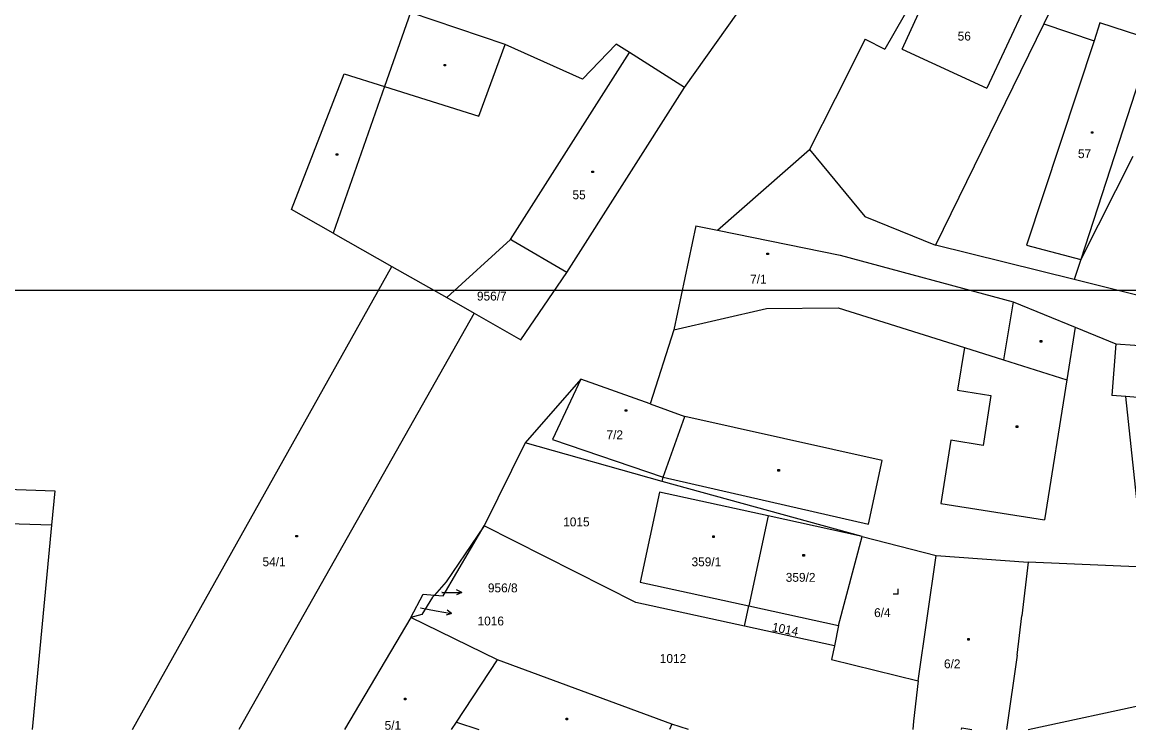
# Model space of a CAD drawing. Extents: x -770973 to -770265, y -1049936 to -1049427.
# Drawn here: x -770637.6 to -770531.6, y -1049934.8 to -1049867 of the extents above; entities that cross this region are included whole.
import ezdxf

# ---------------------------------------------------------------- set-up
doc = ezdxf.new("R2010")
doc.units = 0
for name, color, linetype in [('Vrstva 1', 7, 'Continuous'), ('Vrstva 13', 7, 'Continuous'), ('Vrstva 14', 7, 'Continuous'), ('Vrstva 15', 7, 'Continuous'), ('Vrstva 16', 7, 'Continuous'), ('Vrstva 2', 7, 'Continuous'), ('Vrstva 23', 7, 'Continuous'), ('Vrstva 25', 7, 'Continuous'), ('Vrstva 63', 7, 'Continuous')]:
    doc.layers.add(name, color=color, linetype=linetype)

msp = doc.modelspace()

# ---------------------------------------------------------------- linework, layer by layer
at = {"layer": 'Vrstva 1'}
for p, q in [((-770548.75, -1049858.73), (-770554.96, -1049869.59)), ((-770536.61, -1049860.73), (-770539.76, -1049867.18)), ((-770574.15, -1049873.29), (-770565.62, -1049861.27)), ((-770600.39, -1049866.1), (-770602.87, -1049873.18)), ((-770591.32, -1049869.17), (-770600.39, -1049866.1)), ((-770539.76, -1049867.18), (-770550.11, -1049888.38)), ((-770539.76, -1049867.18), (-770534.94, -1049868.8)), ((-770534.37, -1049867.08), (-770534.94, -1049868.8)), ((-770529.36, -1049868.71), (-770534.37, -1049867.08)), ((-770583.93, -1049872.47), (-770591.32, -1049869.17)), ((-770580.7, -1049869.11), (-770583.93, -1049872.47)), ((-770579.41, -1049869.93), (-770580.7, -1049869.11)), ((-770556.84, -1049868.64), (-770559.74, -1049874.37)), ((-770556.84, -1049868.64), (-770554.96, -1049869.59)), ((-770529.36, -1049868.71), (-770536.21, -1049889.74)), ((-770574.15, -1049873.29), (-770579.41, -1049869.93)), ((-770602.87, -1049873.18), (-770607.79, -1049887.24)), ((-770585.43, -1049890.98), (-770574.15, -1049873.29)), ((-770559.74, -1049874.37), (-770562.2, -1049879.21)), ((-770570.98, -1049886.94), (-770562.2, -1049879.21)), ((-770562.2, -1049879.21), (-770556.89, -1049885.64)), ((-770531.23, -1049879.87), (-770536.21, -1049889.74)), ((-770556.89, -1049885.64), (-770550.11, -1049888.38)), ((-770607.79, -1049887.24), (-770602.19, -1049890.41)), ((-770573.07, -1049886.51), (-770575.19, -1049896.49)), ((-770573.07, -1049886.51), (-770570.98, -1049886.94)), ((-770570.98, -1049886.94), (-770559.25, -1049889.34)), ((-770590.83, -1049887.84), (-770596.92, -1049893.4)), ((-770590.57, -1049887.99), (-770590.83, -1049887.84)), ((-770585.43, -1049890.98), (-770590.57, -1049887.99)), ((-770536.84, -1049891.67), (-770550.11, -1049888.38)), ((-770559.25, -1049889.34), (-770542.68, -1049893.81)), ((-770602.19, -1049890.41), (-770596.92, -1049893.4)), ((-770536.21, -1049889.74), (-770536.84, -1049891.67)), ((-770589.83, -1049897.43), (-770585.43, -1049890.98)), ((-770529.95, -1049893.38), (-770536.84, -1049891.67)), ((-770596.92, -1049893.4), (-770594.31, -1049894.88)), ((-770542.68, -1049893.81), (-770536.74, -1049896.24)), ((-770594.31, -1049894.88), (-770616.82, -1049934.76)), ((-770594.31, -1049894.88), (-770589.83, -1049897.43)), ((-770575.19, -1049896.49), (-770577.44, -1049903.59)), ((-770536.74, -1049896.24), (-770532.86, -1049897.82)), ((-770532.86, -1049897.82), (-770533.23, -1049902.78)), ((-770532.86, -1049897.82), (-770518.01, -1049898.94)), ((-770584.09, -1049901.21), (-770589.41, -1049907.3)), ((-770577.44, -1049903.59), (-770584.09, -1049901.21)), ((-770531.91, -1049902.88), (-770533.23, -1049902.78)), ((-770530.61, -1049914.85), (-770531.91, -1049902.88)), ((-770527.38, -1049903.22), (-770531.91, -1049902.88)), ((-770577.44, -1049903.59), (-770574.11, -1049904.78)), ((-770576.2, -1049910.61), (-770574.11, -1049904.78)), ((-770589.41, -1049907.3), (-770593.33, -1049915.27)), ((-770576.3, -1049911.01), (-770589.41, -1049907.3)), ((-770576.3, -1049911.01), (-770576.2, -1049910.61)), ((-770557.14, -1049916.29), (-770576.3, -1049911.01)), ((-770576.56, -1049912.05), (-770578.41, -1049920.66)), ((-770566.13, -1049914.31), (-770576.56, -1049912.05)), ((-770566.13, -1049914.31), (-770567.99, -1049922.92)), ((-770557.14, -1049916.29), (-770566.13, -1049914.31)), ((-770597.25, -1049921.95), (-770593.33, -1049915.27)), ((-770593.33, -1049915.27), (-770596.97, -1049920.62)), ((-770578.83, -1049922.61), (-770593.33, -1049915.27)), ((-770559.4, -1049924.79), (-770557.14, -1049916.29)), ((-770557.14, -1049916.29), (-770550.07, -1049918.09)), ((-770551.77, -1049930.12), (-770550.07, -1049918.09)), ((-770550.07, -1049918.09), (-770541.25, -1049918.75)), ((-770530.13, -1049919.21), (-770541.25, -1049918.75)), ((-770596.97, -1049920.62), (-770598.09, -1049921.89)), ((-770578.41, -1049920.66), (-770567.99, -1049922.92)), ((-770600.35, -1049924.04), (-770599.19, -1049921.81)), ((-770598.27, -1049922.09), (-770599.29, -1049923.76)), ((-770599.19, -1049921.81), (-770598.09, -1049921.89)), ((-770598.09, -1049921.89), (-770598.27, -1049922.09)), ((-770598.09, -1049921.89), (-770597.25, -1049921.95)), ((-770568.4, -1049924.87), (-770578.83, -1049922.61)), ((-770568.4, -1049924.87), (-770567.99, -1049922.92)), ((-770567.99, -1049922.92), (-770559.4, -1049924.79)), ((-770600.35, -1049924.04), (-770606.7, -1049934.76)), ((-770599.29, -1049923.76), (-770600.35, -1049924.04)), ((-770592.06, -1049928.08), (-770600.35, -1049924.04)), ((-770559.79, -1049926.76), (-770568.4, -1049924.87)), ((-770559.4, -1049924.79), (-770559.79, -1049926.76)), ((-770559.79, -1049926.76), (-770560.08, -1049928.06)), ((-770575.37, -1049934.25), (-770592.06, -1049928.08)), ((-770560.08, -1049928.06), (-770551.77, -1049930.12)), ((-770551.77, -1049930.12), (-770552.23, -1049933.96)), ((-770541.24, -1049934.76), (-770529.39, -1049932.21)), ((-770552.23, -1049933.96), (-770552.3, -1049934.76)), ((-770575.37, -1049934.25), (-770575.59, -1049934.76)), ((-770573.77, -1049934.76), (-770575.37, -1049934.25)), ((-770547.63, -1049934.76), (-770547.61, -1049934.62)), ((-770547.61, -1049934.62), (-770546.65, -1049934.76))]:
    msp.add_line(p, q, dxfattribs=at)
at = {"layer": 'Vrstva 13'}
for p, q in [((-770597.38, -1049921.63), (-770596.98, -1049921.63)), ((-770599.44, -1049923.1), (-770597.92, -1049923.39))]:
    msp.add_line(p, q, dxfattribs=at)
at = {"layer": 'Vrstva 16'}
for p, q in [((-770596.98, -1049921.63), (-770595.48, -1049921.63)), ((-770595.48, -1049921.63), (-770595.98, -1049921.38)), ((-770595.48, -1049921.63), (-770595.98, -1049921.88)), ((-770597.92, -1049923.39), (-770596.45, -1049923.67)), ((-770596.45, -1049923.67), (-770596.89, -1049923.33)), ((-770596.45, -1049923.67), (-770596.98, -1049923.82))]:
    msp.add_line(p, q, dxfattribs=at)
at = {"layer": 'Vrstva 2'}
for p, q in [((-770553.32, -1049869.61), (-770549.58, -1049861.49)), ((-770541.43, -1049865.29), (-770545.19, -1049873.35)), ((-770593.84, -1049876.01), (-770591.32, -1049869.17)), ((-770534.94, -1049868.8), (-770541.42, -1049888.39)), ((-770590.83, -1049887.84), (-770579.41, -1049869.93)), ((-770553.32, -1049869.61), (-770545.19, -1049873.35)), ((-770611.8, -1049884.97), (-770606.74, -1049871.96)), ((-770606.74, -1049871.96), (-770602.87, -1049873.18)), ((-770602.87, -1049873.18), (-770593.84, -1049876.01)), ((-770607.79, -1049887.24), (-770611.8, -1049884.97)), ((-770541.42, -1049888.39), (-770536.21, -1049889.74)), ((-770627.01, -1049934.76), (-770602.19, -1049890.41)), ((-770575.19, -1049896.49), (-770566.31, -1049894.45)), ((-770566.31, -1049894.45), (-770559.44, -1049894.37)), ((-770559.44, -1049894.37), (-770547.34, -1049898.18)), ((-770542.68, -1049893.81), (-770543.61, -1049899.36)), ((-770536.74, -1049896.24), (-770537.54, -1049901.27)), ((-770547.34, -1049898.18), (-770548, -1049902.28)), ((-770547.34, -1049898.18), (-770543.61, -1049899.36)), ((-770543.61, -1049899.36), (-770537.54, -1049901.27)), ((-770584.09, -1049901.21), (-770586.78, -1049907)), ((-770537.54, -1049901.27), (-770539.67, -1049914.69)), ((-770548, -1049902.28), (-770544.81, -1049902.79)), ((-770544.81, -1049902.79), (-770545.57, -1049907.56)), ((-770555.24, -1049909), (-770574.11, -1049904.78)), ((-770586.78, -1049907), (-770576.2, -1049910.61)), ((-770548.66, -1049907.07), (-770549.62, -1049913.11)), ((-770545.57, -1049907.56), (-770548.66, -1049907.07)), ((-770556.54, -1049915.1), (-770555.24, -1049909)), ((-770576.2, -1049910.61), (-770556.54, -1049915.1)), ((-770643.29, -1049911.61), (-770634.44, -1049911.9)), ((-770634.44, -1049911.9), (-770634.76, -1049915.2)), ((-770549.62, -1049913.11), (-770539.67, -1049914.69)), ((-770634.76, -1049915.2), (-770643.67, -1049914.92)), ((-770634.76, -1049915.2), (-770636.62, -1049934.76)), ((-770541.25, -1049918.75), (-770541.85, -1049923.87)), ((-770542.29, -1049927.65), (-770541.85, -1049923.87)), ((-770595.99, -1049934.06), (-770592.06, -1049928.08)), ((-770542.29, -1049927.65), (-770543.33, -1049934.76)), ((-770596.45, -1049934.76), (-770595.99, -1049934.06)), ((-770595.99, -1049934.06), (-770593.84, -1049934.76))]:
    msp.add_line(p, q, dxfattribs=at)
at = {"layer": 'Vrstva 23'}
for q in [(-770554.18, -1049921.79), (-770553.68, -1049921.29)]:
    msp.add_line((-770553.68, -1049921.79), q, dxfattribs=at)
at = {"layer": 'Vrstva 25'}
for p, q in [((-770597.18, -1049871.06), (-770597.03, -1049871.06)), ((-770597.18, -1049871.21), (-770597.18, -1049871.06)), ((-770597.03, -1049871.21), (-770597.18, -1049871.21)), ((-770597.03, -1049871.06), (-770597.03, -1049871.21)), ((-770535.19, -1049877.51), (-770535.04, -1049877.51)), ((-770535.19, -1049877.66), (-770535.19, -1049877.51)), ((-770535.04, -1049877.66), (-770535.19, -1049877.66)), ((-770535.04, -1049877.51), (-770535.04, -1049877.66)), ((-770607.51, -1049879.62), (-770607.36, -1049879.62)), ((-770607.51, -1049879.77), (-770607.51, -1049879.62)), ((-770607.36, -1049879.77), (-770607.51, -1049879.77)), ((-770607.36, -1049879.62), (-770607.36, -1049879.77)), ((-770583.03, -1049881.28), (-770582.88, -1049881.28)), ((-770583.03, -1049881.43), (-770583.03, -1049881.28)), ((-770582.88, -1049881.43), (-770583.03, -1049881.43)), ((-770582.88, -1049881.28), (-770582.88, -1049881.43)), ((-770566.26, -1049889.13), (-770566.11, -1049889.13)), ((-770566.26, -1049889.28), (-770566.26, -1049889.13)), ((-770566.11, -1049889.28), (-770566.26, -1049889.28)), ((-770566.11, -1049889.13), (-770566.11, -1049889.28)), ((-770540.09, -1049897.51), (-770539.94, -1049897.51)), ((-770540.09, -1049897.66), (-770540.09, -1049897.51)), ((-770539.94, -1049897.66), (-770540.09, -1049897.66)), ((-770539.94, -1049897.51), (-770539.94, -1049897.66)), ((-770579.83, -1049904.14), (-770579.68, -1049904.14)), ((-770579.83, -1049904.29), (-770579.83, -1049904.14)), ((-770579.68, -1049904.29), (-770579.83, -1049904.29)), ((-770579.68, -1049904.14), (-770579.68, -1049904.29)), ((-770542.39, -1049905.68), (-770542.24, -1049905.68)), ((-770542.39, -1049905.83), (-770542.39, -1049905.68)), ((-770542.24, -1049905.83), (-770542.39, -1049905.83)), ((-770542.24, -1049905.68), (-770542.24, -1049905.83)), ((-770565.22, -1049909.87), (-770565.07, -1049909.87)), ((-770565.22, -1049910.02), (-770565.22, -1049909.87)), ((-770565.07, -1049910.02), (-770565.22, -1049910.02)), ((-770565.07, -1049909.87), (-770565.07, -1049910.02)), ((-770611.37, -1049916.17), (-770611.22, -1049916.17)), ((-770611.37, -1049916.32), (-770611.37, -1049916.17)), ((-770611.22, -1049916.32), (-770611.37, -1049916.32)), ((-770611.22, -1049916.17), (-770611.22, -1049916.32)), ((-770571.45, -1049916.23), (-770571.3, -1049916.23)), ((-770571.45, -1049916.38), (-770571.45, -1049916.23)), ((-770571.3, -1049916.38), (-770571.45, -1049916.38)), ((-770571.3, -1049916.23), (-770571.3, -1049916.38)), ((-770562.82, -1049918), (-770562.67, -1049918)), ((-770562.82, -1049918.15), (-770562.82, -1049918)), ((-770562.67, -1049918), (-770562.67, -1049918.15)), ((-770562.67, -1049918.15), (-770562.82, -1049918.15)), ((-770547.04, -1049926.06), (-770546.89, -1049926.06)), ((-770547.04, -1049926.21), (-770547.04, -1049926.06)), ((-770546.89, -1049926.21), (-770547.04, -1049926.21)), ((-770546.89, -1049926.06), (-770546.89, -1049926.21)), ((-770600.98, -1049931.77), (-770600.83, -1049931.77)), ((-770600.98, -1049931.92), (-770600.98, -1049931.77)), ((-770600.83, -1049931.77), (-770600.83, -1049931.92)), ((-770600.83, -1049931.92), (-770600.98, -1049931.92)), ((-770585.5, -1049933.69), (-770585.35, -1049933.69)), ((-770585.5, -1049933.84), (-770585.5, -1049933.69)), ((-770585.35, -1049933.84), (-770585.5, -1049933.84)), ((-770585.35, -1049933.69), (-770585.35, -1049933.84))]:
    msp.add_line(p, q, dxfattribs=at)
at = {"layer": 'Vrstva 63'}
msp.add_lwpolyline([(-770858.67, -1049892.7), (-770264.67, -1049892.7), (-770264.67, -1049472.7), (-770858.67, -1049472.7), (-770858.67, -1049892.7)], dxfattribs=at)

# ---------------------------------------------------------------- texts
at = {"layer": 'Vrstva 14'}
for s, height, p in [('956/7', 0.85, (-770594.03, -1049893.68)), ('1015', 0.85, (-770585.77, -1049915.31)), ('956/8', 0.05, (-770597.48, -1049921.63)), ('1016', 0.05, (-770599.51, -1049923.1)), ('1012', 0.85, (-770576.52, -1049928.39))]:
    msp.add_text(s, height=height, dxfattribs=at).set_placement(p)
msp.add_text('1014', height=0.85, rotation=349.0772, dxfattribs=at).set_placement((-770565.83, -1049925.34))
at = {"layer": 'Vrstva 15'}
for s, p in [('56', (-770548, -1049868.78)), ('57', (-770536.48, -1049880.04)), ('55', (-770584.88, -1049883.98)), ('7/1', (-770567.87, -1049892.06)), ('7/2', (-770581.62, -1049906.96)), ('54/1', (-770614.56, -1049919.13)), ('359/1', (-770573.48, -1049919.13)), ('359/2', (-770564.46, -1049920.62)), ('6/4', (-770556, -1049924)), ('6/2', (-770549.31, -1049928.9)), ('5/1', (-770602.87, -1049934.79))]:
    msp.add_text(s, height=0.85, dxfattribs=at).set_placement(p)
at = {"layer": 'Vrstva 16'}
for s, p in [('956/8', (-770592.98, -1049921.63)), ('1016', (-770593.97, -1049924.8))]:
    msp.add_text(s, height=0.85, dxfattribs=at).set_placement(p)

doc.saveas('drawing.dxf')
